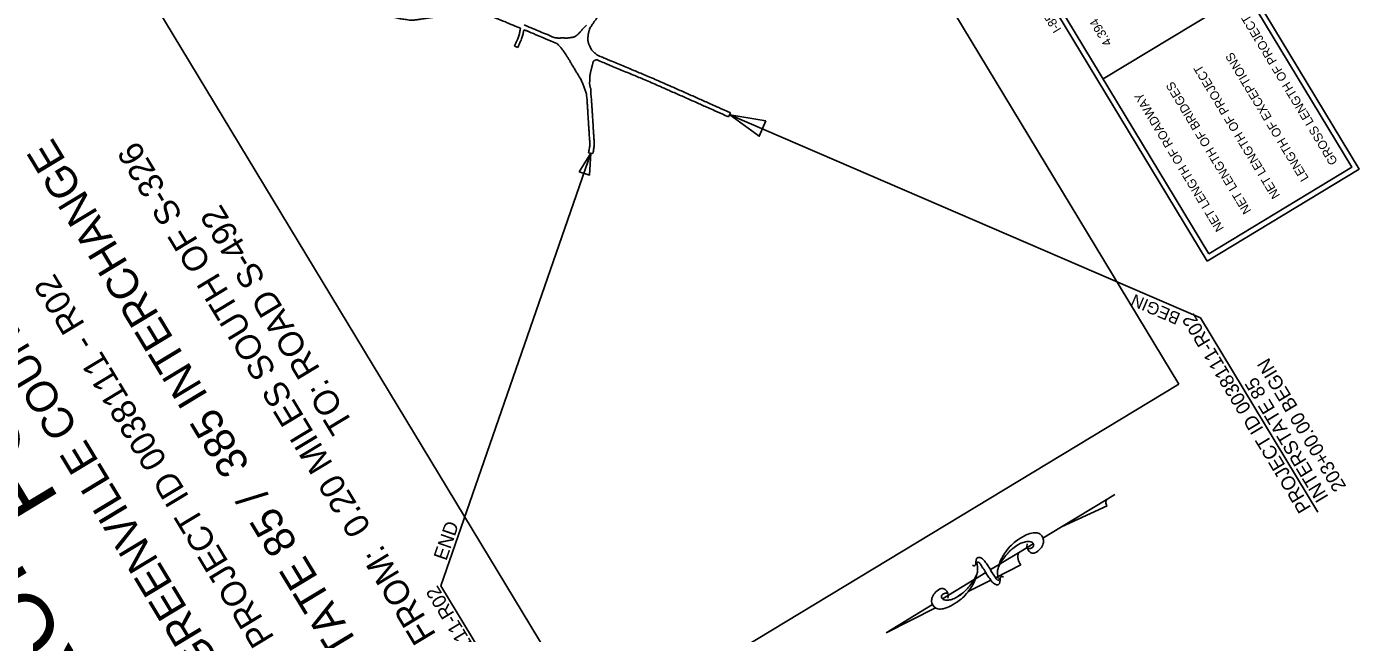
# Model space of a CAD drawing. Extents: x 2640307 to 2643631, y 679117 to 682232.
# Drawn here: x 2642228 to 2642974, y 680585 to 680927 of the extents above; entities that cross this region are included whole.
import ezdxf

# ---------------------------------------------------------------- set-up
doc = ezdxf.new("R2010")
doc.units = 0
for name, color, linetype in [('Level 1', 7, 'Continuous'), ('Level 24', 7, 'Continuous'), ('Level 42', 7, 'Continuous'), ('RD_SHT_Bndy', 7, 'Continuous'), ('RD_SHT_TX', 7, 'Continuous'), ('RD_TX_TitleSht', 7, 'Continuous')]:
    doc.layers.add(name, color=color, linetype=linetype)

msp = doc.modelspace()

# ---------------------------------------------------------------- linework, layer by layer
at = {"layer": 'Level 1'}
for p, q in [((2642809.73, 680645.48), (2642835.88, 680661.28)), ((2642835.88, 680661.28), (2642809.73, 680645.48)), ((2642835.88, 680661.28), (2642839.9, 680663.71)), ((2642809.73, 680645.48), (2642835.57, 680657.24)), ((2642809.73, 680645.48), (2642835.57, 680657.24)), ((2642799.39, 680639.16), (2642809.73, 680645.48)), ((2642776.8, 680625.57), (2642785.6, 680630.89)), ((2642776.8, 680625.57), (2642785.6, 680630.89)), ((2642785.6, 680630.89), (2642793.96, 680635.94)), ((2642770.18, 680621.57), (2642774.77, 680624.34)), ((2642770.18, 680621.57), (2642774.75, 680624.33)), ((2642772.67, 680616.82), (2642786.99, 680624.02)), ((2642786.99, 680624.02), (2642772.67, 680616.82)), ((2642775.22, 680624.61), (2642776.8, 680625.57)), ((2642775.24, 680624.62), (2642776.8, 680625.57)), ((2642786.97, 680624.01), (2642786.99, 680624.02)), ((2642760.72, 680615.86), (2642742.77, 680605.03)), ((2642742.77, 680605.03), (2642760.72, 680615.86)), ((2642757.35, 680609.1), (2642769.99, 680615.48)), ((2642769.99, 680615.48), (2642757.35, 680609.1)), ((2642761.44, 680616.3), (2642767.15, 680619.74)), ((2642761.44, 680616.3), (2642767.15, 680619.74)), ((2642769.81, 680621.34), (2642770.18, 680621.57)), ((2642769.83, 680621.36), (2642770.18, 680621.57)), ((2642711.16, 680585.89), (2642737.29, 680601.69)), ((2642737.29, 680601.69), (2642711.16, 680585.89)), ((2642711.16, 680585.89), (2642738.92, 680599.84)), ((2642711.16, 680585.89), (2642738.92, 680599.84))]:
    msp.add_line(p, q, dxfattribs=at)
for points in [[(2642761.86, 680627.03), (2642761.7, 680625.34), (2642761.61, 680624.41)], [(2642775.07, 680614.13), (2642775.21, 680615.8), (2642775.3, 680616.75)]]:
    msp.add_lwpolyline(points, dxfattribs=at)
for centre, radius, start, end in [((2642837.18, 680659.12), 2.51, 121.21271, 229.341), ((2642837.18, 680659.13), 2.51, 121.21271, 229.341), ((2642795.92, 680620.99), 20.16, 126.39068, 137.92121), ((2642809.62, 680602.4), 43.25, 118.5254, 126.39068), ((2642791.31, 680627.29), 9.92, 92.19319, 107.60792), ((2642796.95, 680625.7), 16.73, 103.12963, 118.5254), ((2642791.13, 680631.95), 5.26, 73.78753, 92.19319), ((2642791.93, 680634.7), 2.4, 46.38887, 73.78753), ((2642794.84, 680634.77), 7.42, 79.92052, 103.12963), ((2642795.46, 680638.26), 3.88, 44.62634, 79.92052), ((2642794.49, 680637.3), 5.24, 14.38606, 44.62634), ((2642795.03, 680637.44), 4.68, 343.65963, 14.38606), ((2642795.34, 680618.1), 21.5, 145.3765, 155.68006), ((2642861.3, 680562.41), 106.45, 140.59084, 142.57352), ((2642811.39, 680607.02), 41.01, 137.92121, 145.3765), ((2642800.79, 680612.13), 28.14, 136.73376, 140.59083), ((2642793.4, 680619.09), 17.98, 127.77874, 136.73376), ((2642803.52, 680606.03), 34.51, 121.31764, 127.77874), ((2642792.2, 680628.63), 6.98, 161.29077, 221.41607), ((2642792.2, 680628.63), 6.98, 161.29077, 221.41607), ((2642792.1, 680624.8), 12.53, 107.60792, 121.31764), ((2642794.81, 680634.73), 4.44, 163.39655, 181.1765), ((2642794.61, 680634.72), 4.23, 181.1765, 199.38575), ((2642794.93, 680634.83), 4.57, 199.38575, 221.38059), ((2642791.47, 680636.27), 3.1, 254.18449, 271.77836), ((2642794.63, 680634.58), 4.18, 221.38059, 244.39366), ((2642791.47, 680636), 2.83, 271.77836, 290.19409), ((2642791.11, 680637), 3.89, 290.19409, 310.46851), ((2642793.86, 680632.97), 2.39, 244.39366, 295.00297), ((2642792.21, 680634.99), 1.99, 17.56245, 46.38886), ((2642792.62, 680635.22), 1.56, 310.46851, 342.77333), ((2642792.79, 680635.17), 1.38, 342.77333, 17.56245), ((2642791.13, 680638.82), 8.85, 295.00297, 320.68942), ((2642791.58, 680638.45), 8.28, 320.68942, 343.65963), ((2642760.75, 680624.92), 1.36, 222.93645, 258.229), ((2642760.6, 680624.23), 0.653, 258.229, 310.20214), ((2642759, 680626.12), 3.13, 310.20214, 319.31615), ((2642759.12, 680626.02), 2.98, 319.31615, 328.65919), ((2642760.04, 680625.46), 1.9, 328.65919, 340.94297), ((2642763.28, 680624.39), 1.51, 147.07299, 162.52917), ((2642762.97, 680626.91), 1.12, 147.55543, 174.70549), ((2642762.88, 680624.64), 1.04, 110.73688, 147.07299), ((2642763.88, 680626.34), 2.19, 128.2471, 147.55543), ((2642742.76, 680621.39), 19.86, 0.48014, 10.20716), ((2642763.19, 680627.21), 1.09, 92.53079, 128.2471), ((2642762.75, 680625), 0.655, 64.53081, 110.73688), ((2642762.27, 680624.01), 1.76, 49.1077, 64.53081), ((2642763.25, 680625.87), 2.43, 68.86846, 92.53079), ((2642761.51, 680623.13), 2.92, 37.1518, 49.1077), ((2642748.32, 680613.13), 19.47, 34.04029, 37.1518), ((2642762.2, 680623.14), 5.35, 53.99814, 68.86846), ((2642646.78, 680544.54), 142.01, 32.88816, 34.04029), ((2642762.72, 680623.86), 4.46, 37.70636, 53.99814), ((2642738.41, 680605.07), 35.19, 35.27982, 37.70636), ((2642670.5, 680557.01), 118.38, 33.95695, 35.27982), ((2642751.52, 680611.58), 20.7, 31.92872, 33.95695), ((2642709.89, 680585.64), 69.75, 30.82386, 31.92872), ((2642782.17, 680619.89), 8.35, 165.45585, 180.48014), ((2642818.46, 680610.48), 45.84, 161.53339, 165.45585), ((2642808.51, 680607.22), 37.55, 150.87773, 155.82226), ((2642808.5, 680607.22), 37.55, 152.3832, 155.82226), ((2642818.46, 680610.48), 45.84, 162.39607, 164.66908), ((2642794.52, 680618.47), 20.6, 155.68006, 161.53338), ((2642787.35, 680619.01), 13.33, 142.57352, 150.87773), ((2642749.09, 680622.37), 13.33, 322.57352, 330.78073), ((2642749.09, 680622.37), 13.33, 322.57352, 330.87773), ((2642741.93, 680622.9), 20.6, 335.68006, 341.53338), ((2642741.93, 680622.9), 20.6, 335.68006, 341.28401), ((2642727.93, 680634.16), 37.55, 330.87773, 335.82226), ((2642717.98, 680630.9), 45.84, 341.53339, 345.45585), ((2642754.27, 680621.49), 8.35, 345.45585, 0.48014), ((2642751.41, 680612.2), 17.4, 30.41867, 32.88816), ((2642711.9, 680589), 63.23, 29.12315, 30.41867), ((2642827.03, 680655.51), 69.75, 210.82386, 211.92872), ((2642827.03, 680655.51), 69.75, 210.84943, 211.92872), ((2642785.4, 680629.57), 20.7, 211.92872, 213.95695), ((2642785.4, 680629.57), 20.7, 211.92872, 213.95695), ((2642866.43, 680684.13), 118.38, 213.95695, 215.27982), ((2642866.43, 680684.13), 118.38, 213.95695, 215.27982), ((2642798.51, 680636.08), 35.19, 215.27982, 217.70636), ((2642798.51, 680636.08), 35.19, 215.27982, 215.83897), ((2642825.02, 680652.15), 63.23, 209.12315, 210.41867), ((2642825.02, 680652.15), 63.23, 209.15704, 210.41867), ((2642785.51, 680628.95), 17.4, 210.41867, 212.88816), ((2642785.5, 680628.95), 17.4, 210.41867, 212.88816), ((2642774.2, 680617.29), 4.46, 217.70636, 233.99814), ((2642890.14, 680696.61), 142.01, 212.88816, 214.04029), ((2642890.14, 680696.61), 142.01, 212.88816, 214.04029), ((2642788.6, 680628.02), 19.47, 214.04029, 215.10467), ((2642788.6, 680628.02), 19.47, 214.04029, 217.1518), ((2642775.41, 680618.02), 2.92, 217.1518, 229.1077), ((2642774.65, 680617.14), 1.76, 229.1077, 244.53081), ((2642793.68, 680619.99), 19.86, 180.48014, 190.20716), ((2642774.18, 680616.14), 0.655, 244.53081, 290.73688), ((2642774.04, 680616.5), 1.04, 290.73688, 327.07299), ((2642773.64, 680616.76), 1.51, 327.07299, 342.52917), ((2642776.88, 680615.69), 1.9, 148.65919, 160.94297), ((2642777.8, 680615.12), 2.98, 139.31615, 148.65919), ((2642777.92, 680615.02), 3.13, 130.20214, 139.31615), ((2642776.32, 680616.92), 0.653, 78.229, 130.20214), ((2642776.17, 680616.22), 1.36, 42.93645, 78.229), ((2642744.87, 680602.92), 8.28, 140.68942, 163.65963), ((2642745.31, 680602.56), 8.85, 115.00297, 140.68942), ((2642742.58, 680608.41), 2.39, 64.39366, 115.00297), ((2642743.82, 680606.15), 1.56, 130.46851, 162.77333), ((2642745.33, 680604.38), 3.89, 110.19409, 130.46851), ((2642741.81, 680606.8), 4.18, 41.38059, 64.39366), ((2642744.97, 680605.37), 2.83, 91.77836, 110.19409), ((2642744.98, 680605.1), 3.1, 74.18449, 91.77836), ((2642741.52, 680606.54), 4.57, 19.38575, 41.38059), ((2642741.83, 680606.65), 4.23, 1.1765, 19.38575), ((2642732.92, 680635.34), 34.51, 301.31764, 307.77874), ((2642732.92, 680635.35), 34.51, 301.31764, 307.77874), ((2642743.04, 680622.28), 17.98, 307.77874, 316.73376), ((2642743.05, 680622.29), 17.98, 307.77874, 316.73376), ((2642725.05, 680634.36), 41.01, 317.92121, 325.3765), ((2642735.64, 680629.24), 28.14, 316.73376, 320.59083), ((2642735.65, 680629.25), 28.14, 316.73376, 320.59083), ((2642725.05, 680634.36), 41.01, 321.97025, 325.3765), ((2642675.13, 680678.96), 106.45, 320.59084, 322.57352), ((2642675.14, 680678.97), 106.45, 320.59084, 322.57352), ((2642741.11, 680623.27), 21.5, 325.3765, 335.68006), ((2642741.11, 680623.27), 21.5, 325.3765, 335.68006), ((2642774.72, 680618.01), 5.35, 233.99814, 248.86846), ((2642773.67, 680615.28), 2.43, 248.86846, 272.53079), ((2642773.73, 680613.94), 1.09, 272.53079, 308.2471), ((2642773.04, 680614.81), 2.19, 308.2471, 327.55543), ((2642773.95, 680614.23), 1.12, 327.55543, 354.70549), ((2642741.41, 680603.94), 4.68, 163.65963, 194.38606), ((2642741.95, 680604.07), 5.24, 194.38606, 224.62634), ((2642741.95, 680604.07), 5.24, 207.11419, 224.62634), ((2642740.98, 680603.12), 3.88, 224.62634, 237.81945), ((2642740.98, 680603.12), 3.88, 224.62634, 259.92052), ((2642743.65, 680606.2), 1.38, 162.77333, 197.56245), ((2642744.24, 680606.39), 1.99, 197.56245, 226.38886), ((2642744.23, 680606.38), 1.99, 222.85191, 226.38886), ((2642744.51, 680606.68), 2.4, 226.38887, 253.78753), ((2642744.51, 680606.68), 2.4, 226.38887, 253.78753), ((2642739.49, 680615.67), 16.73, 283.12963, 298.5254), ((2642745.31, 680609.42), 5.26, 253.78753, 272.19319), ((2642745.31, 680609.43), 5.26, 253.78753, 272.19319), ((2642745.13, 680614.09), 9.92, 272.19319, 287.60792), ((2642745.13, 680614.08), 9.92, 272.19319, 287.60792), ((2642741.63, 680606.65), 4.44, 343.39655, 1.1765), ((2642726.82, 680638.98), 43.25, 298.5254, 306.39068), ((2642744.34, 680616.57), 12.53, 287.60792, 301.31764), ((2642744.35, 680616.57), 12.53, 287.60792, 301.31764), ((2642740.52, 680620.39), 20.16, 306.39068, 317.92121), ((2642741.6, 680606.61), 7.42, 259.92052, 283.12963)]:
    msp.add_arc(centre, radius, start, end, dxfattribs=at)
at = {"layer": 'Level 24'}
msp.add_lwpolyline([(2642538.51, 680845.19), (2642544.98, 680855.73), (2642544.23, 680843.38)], close=True, dxfattribs=at)
at = {"layer": 'Level 42'}
for points in [[(2642891.68, 680795.04), (2642634.9, 681219.84), (2642720.48, 681271.57), (2642977.26, 680846.77)], [(2642892.69, 680799.16), (2642639.02, 681218.82), (2642719.47, 681267.45), (2642973.14, 680847.79)]]:
    msp.add_lwpolyline(points, close=True, dxfattribs=at)
at = {"layer": 'RD_SHT_Bndy'}
msp.add_line((2642833.2, 680897.58), (2642913.69, 680946.23), dxfattribs=at)
msp.add_lwpolyline([(2642875.86, 680725.69), (2642552.94, 681259.91), (2642225.67, 681062.09), (2642548.59, 680527.87)], close=True, dxfattribs=at)
at = {"layer": 'RD_TX_TitleSht'}
for p, q in [((2642888.03, 680763.03), (2642623.12, 680877.37)), ((2642460.68, 680612.26), (2642544.98, 680855.73)), ((2642954.1, 680653.73), (2642888.03, 680763.03)), ((2642460.68, 680612.26), (2642528.08, 680500.75))]:
    msp.add_line(p, q, dxfattribs=at)
for points in [[(2642502.12, 680915.95), (2642503.96, 680915.16)], [(2642548.71, 680910.86), (2642548.72, 680910.86)], [(2642622.5, 680876.17), (2642623.53, 680878.47)], [(2642543.76, 680855.94), (2642546.2, 680855.52)]]:
    msp.add_lwpolyline(points, dxfattribs=at)
msp.add_lwpolyline([(2642643.53, 680873.92), (2642623.12, 680877.37), (2642639.78, 680865.25)], close=True, dxfattribs=at)
for points in [[(2642544.47, 680926.08), (2642545.03, 680926.96), (2642545.62, 680927.83), (2642546.21, 680928.69), (2642547.21, 680930.14), (2642548.27, 680931.54), (2642549.37, 680932.91), (2642550.67, 680934.53), (2642552.02, 680936.09), (2642553.33, 680937.7), (2642554.23, 680938.82), (2642555.08, 680939.97), (2642555.99, 680941.08), (2642557.27, 680942.64), (2642558.67, 680944.09), (2642560.08, 680945.52), (2642561.59, 680947.05), (2642563.13, 680948.53), (2642564.73, 680949.96), (2642565.41, 680950.56), (2642566.09, 680951.16), (2642566.82, 680951.69), (2642568.09, 680952.62), (2642569.4, 680953.51), (2642570.68, 680954.43), (2642572.48, 680955.73), (2642574.26, 680957.04), (2642576.04, 680958.36), (2642577.3, 680959.3), (2642578.51, 680960.28), (2642579.71, 680961.28), (2642580.91, 680962.27), (2642582.04, 680963.32), (2642583.15, 680964.41), (2642584.19, 680965.43), (2642585.21, 680966.48), (2642586.13, 680967.61), (2642587.51, 680969.32), (2642588.9, 680971.04), (2642590.28, 680972.75), (2642591.02, 680973.67), (2642591.78, 680974.58), (2642592.51, 680975.52), (2642593.11, 680976.28), (2642593.45, 680977.21), (2642593.9, 680978.07), (2642594.74, 680979.68), (2642595.57, 680981.3), (2642596.42, 680982.9), (2642597.43, 680984.82), (2642598.45, 680986.74), (2642599.46, 680988.65), (2642600.84, 680991.26), (2642602.24, 680993.85), (2642603.61, 680996.46), (2642605.17, 680999.41), (2642606.73, 681002.37), (2642608.29, 681005.33)], [(2642381.49, 680967.5), (2642383.91, 680965.91), (2642386.34, 680964.31), (2642388.76, 680962.72), (2642390.81, 680961.37), (2642392.68, 680959.76), (2642394.69, 680958.35), (2642399.36, 680955.07), (2642404.07, 680951.84), (2642408.73, 680948.55), (2642411.82, 680946.37), (2642414.9, 680944.18), (2642417.99, 680941.99), (2642420.9, 680939.92), (2642423.77, 680937.8), (2642426.69, 680935.73), (2642428.19, 680934.68), (2642429.93, 680934.02), (2642431.63, 680933.32), (2642433.17, 680932.69), (2642434.69, 680932.12), (2642436.3, 680931.72), (2642437.7, 680931.38), (2642439.1, 680931.18), (2642440.52, 680930.99), (2642442.02, 680930.8), (2642443.53, 680930.54), (2642445.03, 680930.64), (2642446.1, 680930.72), (2642447.18, 680930.86), (2642448.25, 680931.01), (2642450.89, 680931.39), (2642453.53, 680931.77), (2642456.17, 680932.15), (2642458.66, 680932.51), (2642461.15, 680932.86), (2642463.64, 680933.22), (2642465.31, 680933.46), (2642466.98, 680933.75), (2642468.66, 680933.99), (2642469.57, 680934.13), (2642470.49, 680934.23), (2642471.4, 680934.35), (2642472.82, 680934.53), (2642474.21, 680934.85), (2642475.63, 680935.02), (2642477.19, 680935.21), (2642478.78, 680935.05), (2642480.35, 680934.84), (2642481.64, 680934.67), (2642482.93, 680934.45), (2642484.21, 680934.18), (2642485.5, 680933.91), (2642486.81, 680933.73), (2642488.03, 680933.24), (2642489.41, 680932.69), (2642490.78, 680932.12), (2642492.15, 680931.55), (2642496.57, 680929.72), (2642501, 680927.89), (2642505.42, 680926.04)], [(2642505.42, 680926.04), (2642505.31, 680925.18), (2642505.15, 680924.34), (2642504.95, 680923.49), (2642504.69, 680922.34), (2642504.38, 680921.2), (2642503.92, 680920.12), (2642503.32, 680918.73), (2642502.72, 680917.34), (2642502.12, 680915.95)], [(2642503.96, 680915.16), (2642504.57, 680916.58), (2642505.19, 680918.01), (2642505.8, 680919.43), (2642506.3, 680920.59), (2642506.63, 680921.81), (2642506.91, 680923.04), (2642507.08, 680923.77), (2642507.23, 680924.5), (2642507.34, 680925.24)], [(2642507.34, 680925.24), (2642508.18, 680924.89), (2642509.02, 680924.54), (2642509.86, 680924.19), (2642515.2, 680921.95), (2642520.54, 680919.72), (2642525.88, 680917.48)], [(2642524.97, 680920.59), (2642520.26, 680922.57), (2642515.54, 680924.54), (2642510.83, 680926.51), (2642509.74, 680926.97), (2642508.64, 680927.43), (2642507.55, 680927.88)], [(2642542.61, 680927.77), (2642541.92, 680927.08), (2642541.24, 680926.39), (2642540.55, 680925.7), (2642539.87, 680925.01), (2642539.27, 680924.24), (2642538.61, 680923.53), (2642538.01, 680922.88), (2642537.36, 680922.31), (2642536.63, 680921.77), (2642536.16, 680921.41), (2642535.64, 680921.09), (2642535.06, 680921.01), (2642534.54, 680920.93), (2642534.02, 680920.86), (2642533.5, 680920.78), (2642532.96, 680920.71), (2642532.43, 680920.63), (2642531.88, 680920.56), (2642530.91, 680920.43), (2642529.93, 680920.61), (2642528.95, 680920.6), (2642528.21, 680920.59), (2642527.47, 680920.52), (2642526.73, 680920.54), (2642526.14, 680920.56), (2642525.56, 680920.57), (2642524.97, 680920.59)], [(2642548.72, 680910.86), (2642547.98, 680911.47), (2642547.24, 680912.09), (2642546.5, 680912.7), (2642545.63, 680913.43), (2642545.13, 680914.49), (2642544.58, 680915.52), (2642544.17, 680916.28), (2642543.81, 680917.03), (2642543.62, 680917.88), (2642543.44, 680918.69), (2642543.39, 680919.5), (2642543.4, 680920.32), (2642543.41, 680921.01), (2642543.44, 680921.71), (2642543.54, 680922.41), (2642543.66, 680923.16), (2642543.79, 680923.91), (2642544.02, 680924.63), (2642544.17, 680925.11), (2642544.32, 680925.6), (2642544.47, 680926.08)], [(2642525.88, 680917.48), (2642526.28, 680917.17), (2642526.64, 680916.81), (2642526.98, 680916.43), (2642527.72, 680915.63), (2642528.41, 680914.81), (2642529.05, 680913.94), (2642529.68, 680913.1), (2642530.31, 680912.26), (2642530.86, 680911.37), (2642531.78, 680909.88), (2642532.7, 680908.39), (2642533.6, 680906.89), (2642534.67, 680905.1), (2642535.74, 680903.3), (2642536.82, 680901.51), (2642537.72, 680900.01), (2642538.62, 680898.52), (2642539.51, 680897.02)], [(2642545.04, 680888.85), (2642545.01, 680889.85), (2642544.98, 680890.85), (2642544.94, 680891.85), (2642544.93, 680892.31), (2642544.71, 680892.74), (2642544.61, 680893.19), (2642544.48, 680893.76), (2642544.34, 680894.34), (2642544.3, 680894.93), (2642544.27, 680895.42), (2642544.4, 680895.91), (2642544.41, 680896.4), (2642544.42, 680896.98), (2642544.36, 680897.56), (2642544.39, 680898.14), (2642544.44, 680899.02), (2642544.54, 680899.89), (2642544.75, 680900.75), (2642544.91, 680901.43), (2642545.08, 680902.1), (2642545.24, 680902.77), (2642545.44, 680903.58), (2642545.63, 680904.38), (2642545.82, 680905.19), (2642545.97, 680905.8), (2642546.13, 680906.4), (2642546.31, 680907), (2642546.36, 680907.21), (2642546.47, 680907.39), (2642546.63, 680907.56), (2642546.88, 680907.82), (2642547.17, 680907.95), (2642547.5, 680908.05), (2642547.86, 680908.17), (2642548.25, 680908.29), (2642548.6, 680908.18)], [(2642548.6, 680908.18), (2642550.72, 680907.3), (2642552.83, 680906.42), (2642554.95, 680905.54), (2642558.56, 680904.03), (2642562.17, 680902.53), (2642565.78, 680901.02), (2642568.94, 680899.71), (2642572.1, 680898.39), (2642575.25, 680897.06), (2642579.21, 680895.39), (2642583.14, 680893.66), (2642587.07, 680891.92), (2642593.39, 680889.13), (2642599.72, 680886.34), (2642606.03, 680883.53), (2642611.52, 680881.07), (2642617.01, 680878.62), (2642622.5, 680876.17)], [(2642623.53, 680878.47), (2642618.04, 680880.92), (2642612.54, 680883.37), (2642607.05, 680885.83), (2642600.74, 680888.65), (2642594.41, 680891.44), (2642588.09, 680894.23), (2642584.15, 680895.97), (2642580.2, 680897.71), (2642576.24, 680899.38), (2642573.08, 680900.71), (2642569.92, 680902.03), (2642566.75, 680903.35), (2642563.14, 680904.85), (2642559.53, 680906.36), (2642555.91, 680907.86), (2642553.51, 680908.86), (2642551.11, 680909.86), (2642548.71, 680910.86)], [(2642539.51, 680897.02), (2642539.92, 680896.11), (2642540.33, 680895.19), (2642540.72, 680894.27), (2642541.16, 680893.27), (2642541.48, 680892.23), (2642541.82, 680891.19), (2642542.16, 680890.13), (2642542.52, 680889.07), (2642542.65, 680887.96), (2642542.81, 680886.68), (2642542.91, 680885.39), (2642542.99, 680884.1), (2642543.14, 680881.86), (2642543.29, 680879.61), (2642543.42, 680877.37), (2642543.54, 680875.56), (2642543.64, 680873.75), (2642543.75, 680871.94), (2642543.89, 680869.73), (2642544.04, 680867.52), (2642544.18, 680865.31), (2642544.25, 680864.26), (2642544.36, 680863.21), (2642544.43, 680862.16), (2642544.5, 680861.19), (2642544.48, 680860.19), (2642544.32, 680859.23), (2642544.13, 680858.13), (2642543.94, 680857.03), (2642543.76, 680855.94)], [(2642546.2, 680855.52), (2642546.4, 680856.67), (2642546.59, 680857.82), (2642546.79, 680858.97), (2642546.97, 680860.04), (2642546.99, 680861.13), (2642546.92, 680862.21), (2642546.84, 680863.3), (2642546.72, 680864.39), (2642546.65, 680865.49), (2642546.51, 680867.69), (2642546.36, 680869.89), (2642546.23, 680872.09), (2642546.12, 680873.9), (2642546.01, 680875.71), (2642545.9, 680877.53), (2642545.76, 680879.78), (2642545.61, 680882.03), (2642545.46, 680884.29), (2642545.37, 680885.66), (2642545.26, 680887.02), (2642545.11, 680888.38), (2642545.09, 680888.54), (2642545.06, 680888.7), (2642545.04, 680888.85)]]:
    msp.add_open_spline(points, degree=3, dxfattribs=at)

# ---------------------------------------------------------------- texts
at = {"layer": 'RD_SHT_TX'}
for s, height, rotation, p in [('4.394                              2.551                              9.035                              2.867                             18.757', 5.0001, 121.15134, (2642838.31, 680917.75)), ('I-85', 5, 121.15134, (2642809.86, 680925.34)), ('GROSS LENGTH OF PROJECT', 5.0001, 121.15134, (2642965.39, 680850.93)), ('PROPOSED PLANS', 37.5, 121.15134, (2642285.9, 680523.05)), ('LENGTH OF EXCEPTIONS', 5.0001, 121.15134, (2642949.06, 680841.7)), ('NET LENGTH OF PROJECT', 5.0001, 121.15134, (2642932.93, 680831.95)), ('NET LENGTH OF BRIDGES', 5.0001, 121.15134, (2642916.75, 680823.34)), ('NET LENGTH OF ROADWAY', 5.0001, 121.15134, (2642901.35, 680813.45)), ('INTERSTATE 85 /  385 INTERCHANGE', 17.5, 121.14982, (2642459.22, 680505.53)), ('FROM:  0.20 MILES SOUTH OF S-326', 14, 121.14982, (2642458.33, 680584.66)), ('TO: ROAD S-492', 14, 121.14982, (2642411.9, 680703.05)), ('PROJECT ID 0038111 - R02', 14, 121.15134, (2642367.3, 680583)), ('GREENVILLE COUNTY', 17.5, 121.14982, (2642336.5, 680569.72)), ('FOR', 37.5, 121.15134, (2642246.52, 680660.71)), ('END', 7.825, 70.902, (2642463.7, 680626.03))]:
    msp.add_text(s, height=height, rotation=rotation, dxfattribs=at).set_placement(p)
at = {"layer": 'RD_TX_TitleSht'}
for s, height, rotation, p in [('BEGIN', 6.896, 156.65524, (2642877.24, 680765.32)), ('PROJECT ID 0038111-R02', 7.825, 121.15134, (2642950.42, 680656.23)), ('203+00.00 BEGIN', 7.825, 121.15134, (2642970.23, 680668.21)), ('INTERSTATE 85 ', 7.825, 121.15134, (2642960.32, 680662.22)), ('PROJECT ID 0038111-R02', 7.825, 121.15134, (2642525.02, 680503.02))]:
    msp.add_text(s, height=height, rotation=rotation, dxfattribs=at).set_placement(p)

doc.saveas('drawing.dxf')
